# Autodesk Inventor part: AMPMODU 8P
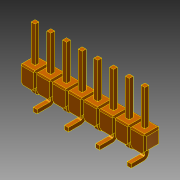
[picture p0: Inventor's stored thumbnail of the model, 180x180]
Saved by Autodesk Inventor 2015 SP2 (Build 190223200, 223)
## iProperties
Created: 2015-08
Part Number: AMPMODU 8P
Material: Allgemein
Document SubType Name: Modeling
Designer: rYan
Density: 1 g/cm^3
Appearance: Vorgabe
Author: workeradm
Title: c-1241150-8-b-3d.igs
Organization: Unknown
Description: PTC IGES file: c-1241150-8-b-3d.igs
Sending System: Creo Parametric by Parametric Technology Corporation
Preprocessor: 2013050
Minimum Resolution: 0.00233
Sending System Product ID: C-1241150-8
Receiving System Product ID: C-1241150-8
Sent Units: Millimeter
Translation Standard: USPRO/IPO100 IGES 5.2
Author: rYan
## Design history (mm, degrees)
node "c-1241150-8-b-3d1"
feature "Zusammengesetzt1"
node "Fläche1"
